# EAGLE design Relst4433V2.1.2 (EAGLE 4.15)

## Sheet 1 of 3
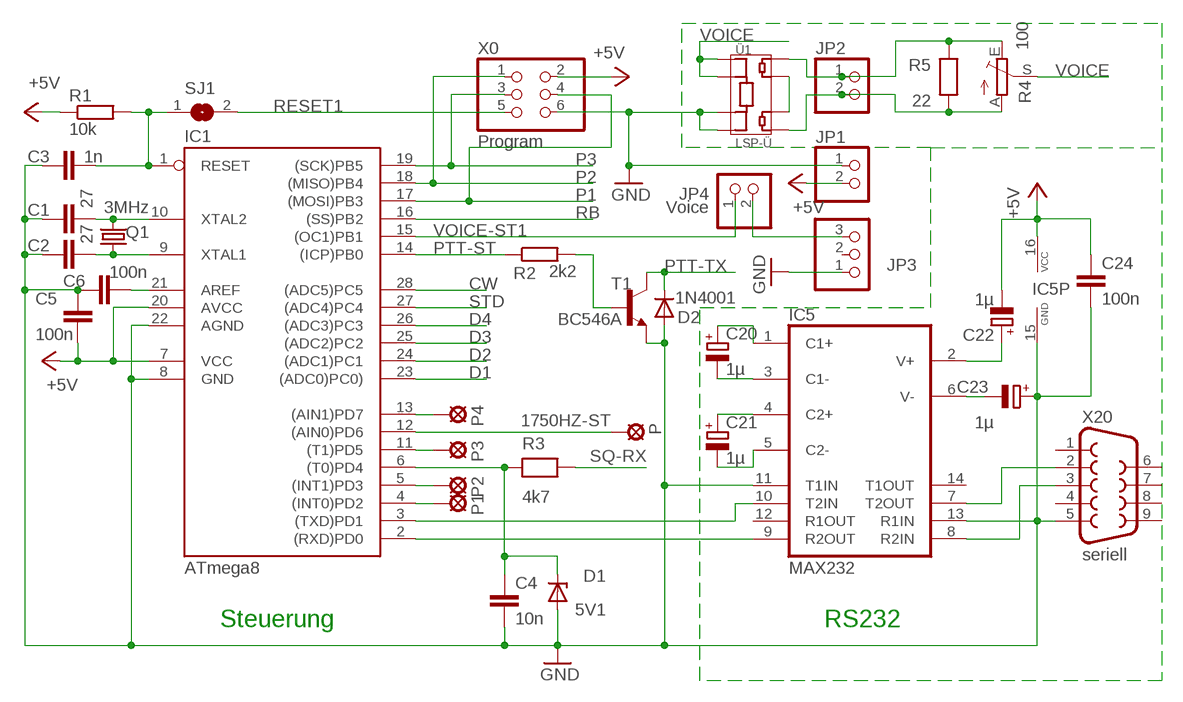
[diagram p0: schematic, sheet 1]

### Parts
C1  27  C-EU025-024X044  [C025-024X044]
C2  27  C-EU025-024X044  [C025-024X044]
C3  1n  C-EU025-024X044  [C025-024X044]
C4  10n  C-EU025-024X044  [C025-024X044]
C5  100n  C-EU025-024X044  [C025-024X044]
C6  100n  C-EU025-024X044  [C025-024X044]
C20  1µ  CPOL-EUE2-5  [E2-5]
C21  1µ  CPOL-EUE2-5  [E2-5]
C22  1µ  CPOL-EUE2-5  [E2-5]
C23  1µ  CPOL-EUE2-5  [E2-5]
C24  100n  C-EU025-024X044  [C025-024X044]
D1  5V1  ZENER-DIODEZD-7.5  [ZDIO-7.5]
D2  1N4001  DIODE-C1702-05  [C1702-05]
IC1  ATmega8  AT90S4433P  [DIL28-3]
IC5  MAX232  [DIL16]
JP1  PINHD-1X2  [1X02]
JP2  PINHD-1X2  [1X02]
JP3  PINHD-1X3  [1X03]
JP4  Voice  PINHD-1X2  [1X02]
P  SE11  [SE11]
P1  SE11  [SE11]
P2  SE11  [SE11]
P3  SE11  [SE11]
P4  SE11  [SE11]
Q1  3MHz  CRYTALHC18U-V  [HC18U-V]
R1  10k  R-EU_0207/2V  [0207/2V]
R2  2k2  R-EU_0414/5V  [0414V]
R3  4k7  RESEU-10  [R-10]
R4  100  TRIM_EU-PT10S  [PT-10S]
R5  22  RESEU-10  [R-10]
SJ1  SJ  [SJ]
T1  BC546A  [TO92-EBC]
X0  Program  PINHD-2X3  [2X03]
X20  seriell  F09H  [F09H]
Ü1  LSP-Ü  LSP-ÜBERTRAGER  [LSP-ÜBERTRAGER]

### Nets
1750HZ-ST: IC1.12((AIN0)PD6) P.MP ; also sheet 2
+5V: C5.2 C22.- C24.1 IC1.7(VCC) IC1.20(AVCC) IC5.16(VCC) JP1.2 R1.1 X0.2 ; also sheet 2,3
AREF: C6.2 IC1.21(AREF)
CW: IC1.28((ADC5)PC5) ; also sheet 2
D1: IC1.23((ADC0)PC0)) ; also sheet 2
D2: IC1.24((ADC1)PC1) ; also sheet 2
D3: IC1.25((ADC2)PC2) ; also sheet 2
D4: IC1.26((ADC3)PC3) ; also sheet 2
GND: C1.1 C2.1 C3.1 C4.2 C5.1 C6.1 C23.+ C24.2 D1.A D2.A IC1.8(GND) IC1.22(AGND) IC5.11(T1IN) IC5.13(R1IN) IC5.15(GND) JP1.1 JP3.1 T1.E X0.6 X20.5 Ü1.9 Ü1.P$10 ; also sheet 2,3
N$1: C1.2 IC1.10(XTAL2) Q1.2
N$2: C2.2 IC1.9(XTAL1) Q1.1
N$3: C21.- IC5.5(C2-)
N$4: IC1.2((RXD)PD0) IC5.9(R2OUT)
N$5: C21.+ IC5.4(C2+)
N$6: IC1.3((TXD)PD1) IC5.10(T2IN)
N$13: C20.+ IC5.1(C1+)
N$14: C20.- IC5.3(C1-)
N$15: IC5.8(R2IN) X20.3
N$16: IC5.7(T2OUT) X20.2
N$22: R2.2 T1.B
N$61: Ü1.2 Ü1.4
N$64: JP2.1 R4.E R5.2 Ü1.5
N$66: JP2.2 R4.A R5.1 Ü1.1
N$73: C22.+ IC5.2(V+)
N$74: C23.- IC5.6(V-)
N$84: IC1.13((AIN1)PD7) P4.MP
N$85: IC1.11((T1)PD5) P3.MP
N$86: IC1.5((INT1)PD3) P2.MP
N$87: IC1.4((INT0)PD2) P1.MP
P1: IC1.17((MOSI)PB3) X0.4 ; also sheet 3
P2: IC1.18((MISO)PB4) X0.1 ; also sheet 3
P3: IC1.19((SCK)PB5) X0.3 ; also sheet 3
PTT-ST: IC1.14((ICP)PB0) R2.1
PTT-TX: D2.C T1.C ; also sheet 3
RB: IC1.16((SS)PB2) ; also sheet 2
RESET: C3.2 IC1.1(RESET) R1.2 SJ1.1 ; also sheet 2
RESET1: SJ1.2 X0.5 ; also sheet 2
SQ-RX: R3.2 ; also sheet 3
SQUELCH: C4.1 D1.C IC1.6((T0)PD4) R3.1
STD: IC1.27((ADC4)PC4) ; also sheet 2
VOICE: R4.S Ü1.7 Ü1.P$6 ; also sheet 2
VOICE-ST: JP3.3 JP4.2
VOICE-ST1: IC1.15((OC1)PB1) JP4.1
Unconnected: IC5.12(R1OUT) IC5.14(T1OUT) JP3.2 X20.1 X20.4 X20.6 X20.7 X20.8 X20.9

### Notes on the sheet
- Steuerung | RS232

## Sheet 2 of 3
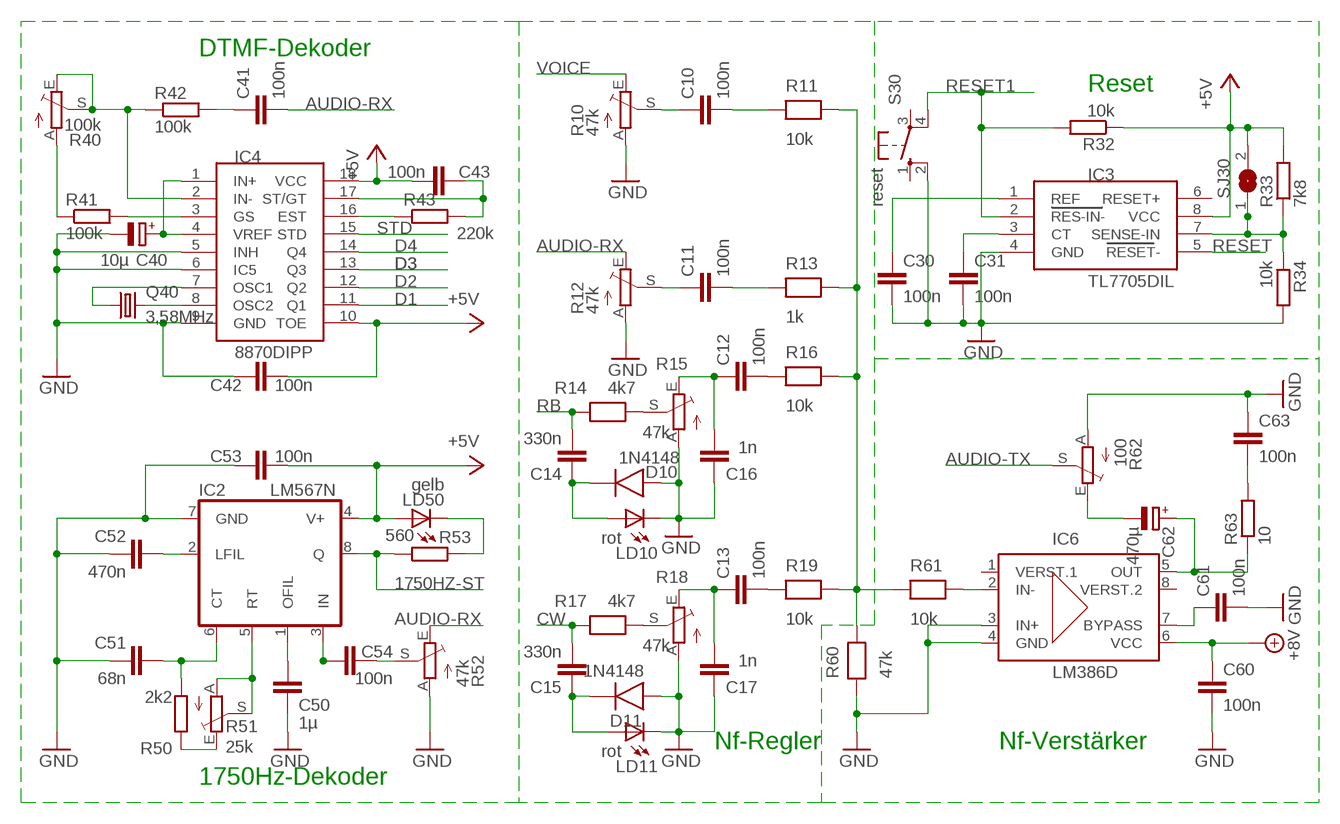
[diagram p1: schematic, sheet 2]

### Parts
C10  100n  C-EU050-025X075  [C050-025X075]
C11  100n  C-EU050-025X075  [C050-025X075]
C12  100n  C-EU050-025X075  [C050-025X075]
C13  100n  C-EU050-025X075  [C050-025X075]
C14  330n  C-EU050-025X075  [C050-025X075]
C15  330n  C-EU050-025X075  [C050-025X075]
C16  1n  C-EU050-025X075  [C050-025X075]
C17  1n  C-EU050-025X075  [C050-025X075]
C30  100n  C-EU050-025X075  [C050-025X075]
C31  100n  C-EU050-025X075  [C050-025X075]
C40  10µ  CPOL-EUE2-5  [E2-5]
C41  100n  C-EU050-025X075  [C050-025X075]
C42  100n  C-EU050-025X075  [C050-025X075]
C43  100n  C-EU050-025X075  [C050-025X075]
C50  1µ  C-EU050-025X075  [C050-025X075]
C51  68n  C-EU050-025X075  [C050-025X075]
C52  470n  C-EU050-025X075  [C050-025X075]
C53  100n  C-EU050-025X075  [C050-025X075]
C54  100n  C-EU050-025X075  [C050-025X075]
C60  100n  C-EU050-025X075  [C050-025X075]
C61  100n  C-EU050-025X075  [C050-025X075]
C62  470µ  CPOL-EUE5-10.5  [E5-10,5]
C63  100n  C-EU050-025X075  [C050-025X075]
D10  1N4148  DIODE-2,5  [D-2,5]
D11  1N4148  DIODE-2,5  [D-2,5]
IC2  LM567N  [DIL08]
IC3  TL7705DIL  [DIL8]
IC4  8870DIPP  [DIL18]
IC6  LM386D  [DIL8]
LD10  rot  LED3MM  [LED3MM]
LD11  rot  LED3MM  [LED3MM]
LD50  gelb  LED3MM  [LED3MM]
Q40  3,58MHz  CRYTALHC18U-V  [HC18U-V]
R10  47k  TRIM_EU-PT10  [PT-10]
R11  10k  RESEU-10  [R-10]
R12  47k  TRIM_EU-PT10  [PT-10]
R13  1k  RESEU-10  [R-10]
R14  4k7  RESEU-10  [R-10]
R15  47k  TRIM_EU-PT10  [PT-10]
R16  10k  RESEU-10  [R-10]
R17  4k7  RESEU-10  [R-10]
R18  47k  TRIM_EU-PT10  [PT-10]
R19  10k  RESEU-10  [R-10]
R32  10k  R-EU_0207/2V  [0207/2V]
R33  7k8  R-EU_0207/2V  [0207/2V]
R34  10k  R-EU_0207/10  [0207/10]
R40  100k  TRIM_EU-PT10  [PT-10]
R41  100k  R-EU_0207/10  [0207/10]
R42  100k  R-EU_0207/10  [0207/10]
R43  220k  R-EU_0207/10  [0207/10]
R50  2k2  R-EU_0207/10  [0207/10]
R51  25k  TRIM_EU-PT10  [PT-10]
R52  47k  TRIM_EU-PT10  [PT-10]
R53  560  R-EU_0207/10  [0207/10]
R60  47k  RESEU-10  [R-10]
R61  10k  RESEU-10  [R-10]
R62  100  TRIM_EU-PT10  [PT-10]
R63  10  R-EU_0207/10  [0207/10]
S30  reset  10-XX  [B3F-10XX]
SJ30  SJ  [SJ]

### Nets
1750HZ-ST: IC2.8(Q) R53.1 ; also sheet 1
+5V: C42.2 C43.2 C53.2 IC2.4(V+) IC3.8(VCC) IC4.10(TOE) IC4.18(VCC) LD50.A R32.1 R33.2 SJ30.2 ; also sheet 1,3
+8V: C60.1 IC6.6(VCC) ; also sheet 3
AUDIO-RX: C41.2 R12.E R52.E ; also sheet 3
AUDIO-TX: R62.S ; also sheet 3
AUDIO-TX-1: R11.2 R13.2 R16.2 R19.2 R60.2 R61.1
CW: C15.2 R17.1 ; also sheet 1
D1: IC4.11(Q1) ; also sheet 1
D2: IC4.12(Q2) ; also sheet 1
D3: IC4.13(Q3) ; also sheet 1
D4: IC4.14(Q4) ; also sheet 1
GND: C16.1 C17.1 C30.2 C31.2 C40.- C42.1 C50.2 C51.1 C52.1 C53.1 C60.2 C61.2 C63.1 D10.1(A) D11.1(A) IC2.7(GND) IC3.4(GND) IC4.5(INH) IC4.6(IC5) IC4.9(GND) IC6.3(IN+) IC6.4(GND) LD10.K(C) LD11.K(C) R10.A R12.A R15.A R18.A R34.2 R52.A R60.1 R62.A S30.2(S1) ; also sheet 1,3
N$8: LD50.K(C) R53.2
N$10: C30.1 IC3.1(REF)
N$12: R17.2 R18.S
N$18: C54.2 R52.S
N$20: C40.+ IC4.1(IN+) IC4.4(VREF)
N$21: C12.1 C16.2 R15.E
N$23: C31.1 IC3.3(CT)
N$24: IC4.8(OSC2) Q40.2
N$25: IC4.7(OSC1) Q40.1
N$26: IC4.2(IN-) R40.E R40.S R42.1
N$27: IC4.3(GS) R41.2
N$28: R40.A R41.1
N$29: C41.1 R42.2
N$30: C13.1 C17.2 R18.E
N$31: IC4.16(EST) R43.1
N$32: C43.1 IC4.17(ST/GT) R43.2
N$33: C10.2 R11.1
N$35: C12.2 R16.1
N$36: C13.2 R19.1
N$37: C54.1 IC2.3(IN)
N$40: C50.1 IC2.1(OFIL)
N$44: IC2.5(RT) R51.A R51.S
N$47: R50.1 R51.E
N$48: C51.2 IC2.6(CT) R50.2
N$51: C52.2 IC2.2(LFIL)
N$65: C11.2 R13.1
N$68: C11.1 R12.S
N$71: C14.1 D10.2(K) LD10.A
N$72: C10.1 R10.S
N$75: C63.2 R63.2
N$76: IC6.2(IN-) R61.2
N$77: C62.- R62.E
N$78: IC3.7(SENSE-IN) R33.1 R34.1 SJ30.1
N$79: C15.1 D11.2(K) LD11.A
N$81: C61.1 IC6.7(BYPASS)
N$82: C62.+ IC6.5(OUT) R63.1
N$89: R14.2 R15.S
RB: C14.2 R14.1 ; also sheet 1
RESET: IC3.5(RESET-) ; also sheet 1
RESET1: IC3.2(RES-IN-) R32.2 S30.4(P1) ; also sheet 1
STD: IC4.15(STD) ; also sheet 1
VOICE: R10.E ; also sheet 1
Unconnected: IC3.6(RESET+) IC6.1(VERST.1) IC6.8(VERST.2) S30.1(S) S30.3(P)

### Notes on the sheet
- DTMF-Dekoder
- Reset
- Nf-Regler | Nf-Verstärker
- 1750Hz-Dekoder

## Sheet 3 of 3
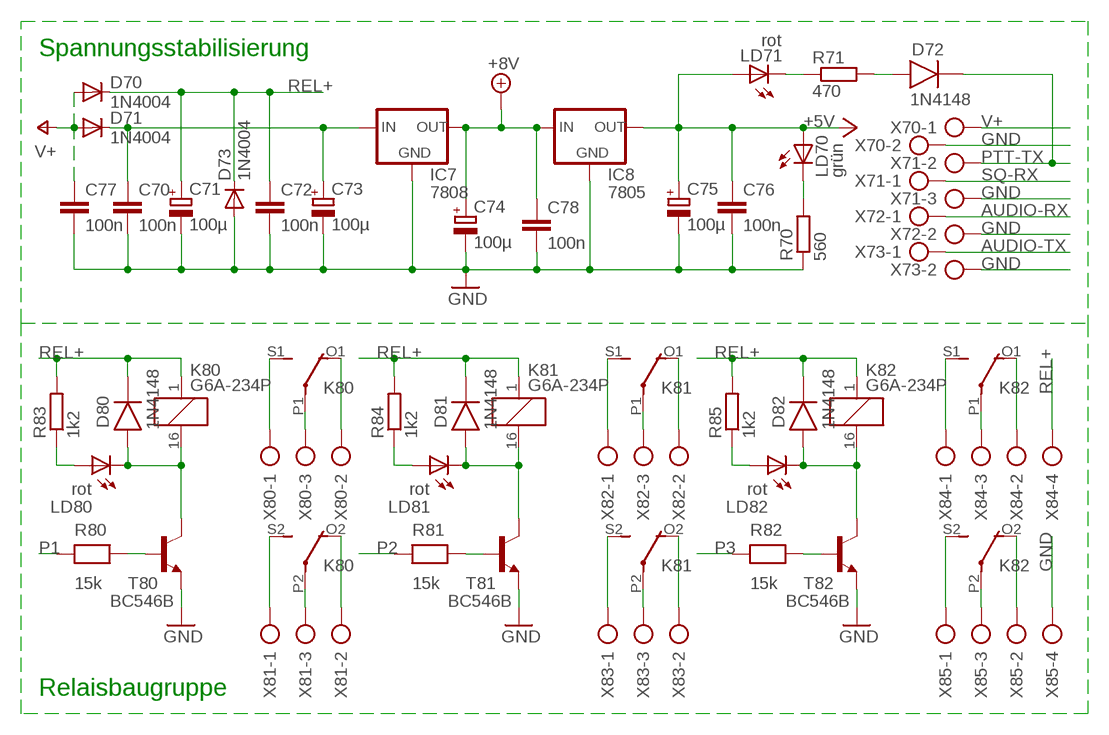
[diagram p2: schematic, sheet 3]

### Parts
C70  100n  C-EU050-025X075  [C050-025X075]
C71  100µ  CPOL-EUE5-10.5  [E5-10,5]
C72  100n  C-EU050-025X075  [C050-025X075]
C73  100µ  CPOL-EUE5-10.5  [E5-10,5]
C74  100µ  CPOL-EUE5-10.5  [E5-10,5]
C75  100µ  CPOL-EUE5-10.5  [E5-10,5]
C76  100n  C-EU050-025X075  [C050-025X075]
C77  100n  C-EU050-025X075  [C050-025X075]
C78  100n  C-EU050-025X075  [C050-025X075]
D70  1N4004  [DO41-10]
D71  1N4004  [DO41-10]
D72  1N4148  DIODE-2,5  [D-2,5]
D73  1N4004  1N4148  [DO35-10]
D80  1N4148  DIODE-7,5  [D-7,5]
D81  1N4148  DIODE-7,5  [D-7,5]
D82  1N4148  DIODE-7,5  [D-7,5]
IC7  7808  78XXS  [78XXS]
IC8  7805  78XXS  [78XXS]
K80  G6A-234P  [G6A-234P]
K81  G6A-234P  [G6A-234P]
K82  G6A-234P  [G6A-234P]
LD70  grün  LED3MM  [LED3MM]
LD71  rot  LED3MM  [LED3MM]
LD80  rot  LED3MM  [LED3MM]
LD81  rot  LED3MM  [LED3MM]
LD82  rot  LED3MM  [LED3MM]
R70  560  R-EU_0207/10  [0207/10]
R71  470  R-EU_0414/5V  [0414V]
R80  15k  RESEU-10  [R-10]
R81  15k  RESEU-10  [R-10]
R82  15k  RESEU-10  [R-10]
R83  1k2  R-EU_0207/2V  [0207/2V]
R84  1k2  R-EU_0207/2V  [0207/2V]
R85  1k2  R-EU_0207/2V  [0207/2V]
T80  BC546B  [TO92-EBC]
T81  BC546B  [TO92-EBC]
T82  BC546B  [TO92-EBC]
X70  AK500/2  [AK500/2]
X71  AK500/3  [AK500/3]
X72  AK500/2  [AK500/2]
X73  AK500/2  [AK500/2]
X80  AK500/3  [AK500/3]
X81  AK500/3  [AK500/3]
X82  AK500/3  [AK500/3]
X83  AK500/3  [AK500/3]
X84  AK500/4  [AK500/4]
X85  AK500/4  [AK500/4]

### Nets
+5V: C75.+ C76.1 IC8.OUT LD70.A LD71.A ; also sheet 1,2
+8V: C74.+ C78.1 IC7.OUT IC8.IN ; also sheet 2
AUDIO-RX: X72.1 ; also sheet 2
AUDIO-TX: X73.1 ; also sheet 2
GND: C70.2 C71.- C72.2 C73.- C74.- C75.- C76.2 C77.2 C78.2 D73.A IC7.GND IC8.GND R70.1 T80.E T81.E T82.E X70.2 X71.3 X72.2 X73.2 X85.4 ; also sheet 1,2
N$7: LD71.K(C) R71.1
N$9: K80.P1(2:P) X80.3
N$11: D72.1(A) R71.2
N$17: K80.P2(3:P) X81.3
N$19: K81.P1(2:P) X82.3
N$34: K81.P2(3:P) X83.3
N$38: K82.P1(2:P) X84.3
N$39: K82.P2(3:P) X85.3
N$41: K80.S1(2:S) X80.1
N$42: K80.O1(2:O) X80.2
N$43: K80.S2(3:S) X81.1
N$45: K80.O2(3:O) X81.2
N$46: K81.S2(3:S) X83.1
N$49: K81.O2(3:O) X83.2
N$50: K81.S1(2:S) X82.1
N$52: K81.O1(2:O) X82.2
N$53: K82.S1(2:S) X84.1
N$54: D80.1(A) K80.16 LD80.K(C) T80.C
N$55: K82.O1(2:O) X84.2
N$56: R81.2 T81.B
N$57: K82.S2(3:S) X85.1
N$58: K82.O2(3:O) X85.2
N$59: D81.1(A) K81.16 LD81.K(C) T81.C
N$60: LD80.A R83.1
N$62: R80.2 T80.B
N$63: R82.2 T82.B
N$67: C70.1 C73.+ D71.C IC7.IN
N$69: D82.1(A) K82.16 LD82.K(C) T82.C
N$70: LD70.K(C) R70.2
N$88: LD81.A R84.1
N$90: LD82.A R85.1
P1: R80.1 ; also sheet 1
P2: R81.1 ; also sheet 1
P3: R82.1 ; also sheet 1
PTT-TX: D72.2(K) X71.2 ; also sheet 1
REL+: C71.+ C72.1 D70.C D73.C D80.2(K) D81.2(K) D82.2(K) K80.1 K81.1 K82.1 R83.2 R84.2 R85.2 X84.4
SQ-RX: X71.1 ; also sheet 1
V+: C77.1 D70.A D71.A X70.1

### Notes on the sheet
- Spannungsstabilisierung
- Relaisbaugruppe

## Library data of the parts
C1-C6 C10-C17 C24 C30 C31 C41-C43 C50-C54 C60 C61 C63 C70 C72 C76-C78 = rcl:C-EU: CAPACITOR, European symbol
C20-C23 C40 C62 C71 C73-C75 = rcl:CPOL-EU: POLARIZED CAPACITOR, European symbol
D1 = diode:ZENER-DIODE: Z-Diode
D2 = diode:DIODE-: DIODE
D10 D11 D72 = discrete:DIODE-2,5
D70 D71 = diode:1N4004: DIODE
D73 = diode:1N4148: DIODE
D80-D82 = discrete:DIODE-7,5
IC1 = atmel:AT90S4433: MICROCONTROLLER 4 Kbytes FLASH 128 bytes SRAM 256 bytes EEPROM UART 6-channel 10 bit ADC
IC2 = linear:*567: TONE DECODER
IC3 = Eigenbaua:TL7705: Power On Reset Generator Precision Voltage Sensor
IC4 = Eigenbaua:8870*: DTMF-Dekoder
IC5 = maxim:MAX232: RS232 TRANSEIVER
IC6 = Eigenbaua:LM386: Nf-Verstärker
IC7 IC8 = v-reg:78XXS: VOLTAGE REGULATOR
JP1 JP2 JP4 = pinhead:PINHD-1X2: PIN HEADER
JP3 = pinhead:PINHD-1X3: PIN HEADER
K80-K82 = relay:G6A-234P: RELAY 2 x switch, 0.3 A/125 V AC, 1 A/30 V DC, Omron
LD10 LD11 LD50 LD70 LD71 LD80-LD82 = led:LED: LED
P P1-P4 = solpad:SE11: SOLDER PAD
Q1 Q40 = crystal:CRYTAL: CRYSTAL
R1 R2 R32-R34 R41-R43 R50 R53 R63 R70 R71 R83-R85 = rcl:R-EU_: RESISTOR, European symbol
R3 R5 R11 R13 R14 R16 R17 R19 R60 R61 R80-R82 = discrete:RESEU-10
R4 R10 R12 R15 R18 R40 R51 R52 R62 = pot:TRIM_EU-: POTENTIOMETER
S30 = switch-omron:10-XX: OMRON SWITCH
SJ1 SJ30 = jumper:SJ: SMD solder JUMPER
T1 T80-T82 = transistor-npn:BC546*: NPN Transistor
X0 = pinhead:PINHD-2X3: PIN HEADER
X20 = con-subd:F09: SUB-D
X70 X72 X73 = con-ptr500:AK500/2: CONNECTOR
X71 X80-X83 = con-ptr500:AK500/3: CONNECTOR
X84 X85 = con-ptr500:AK500/4: CONNECTOR
Ü1 = Eigenbaua:LSP-ÜBERTRAGER*: Laursprecherübertager für Voice-Module

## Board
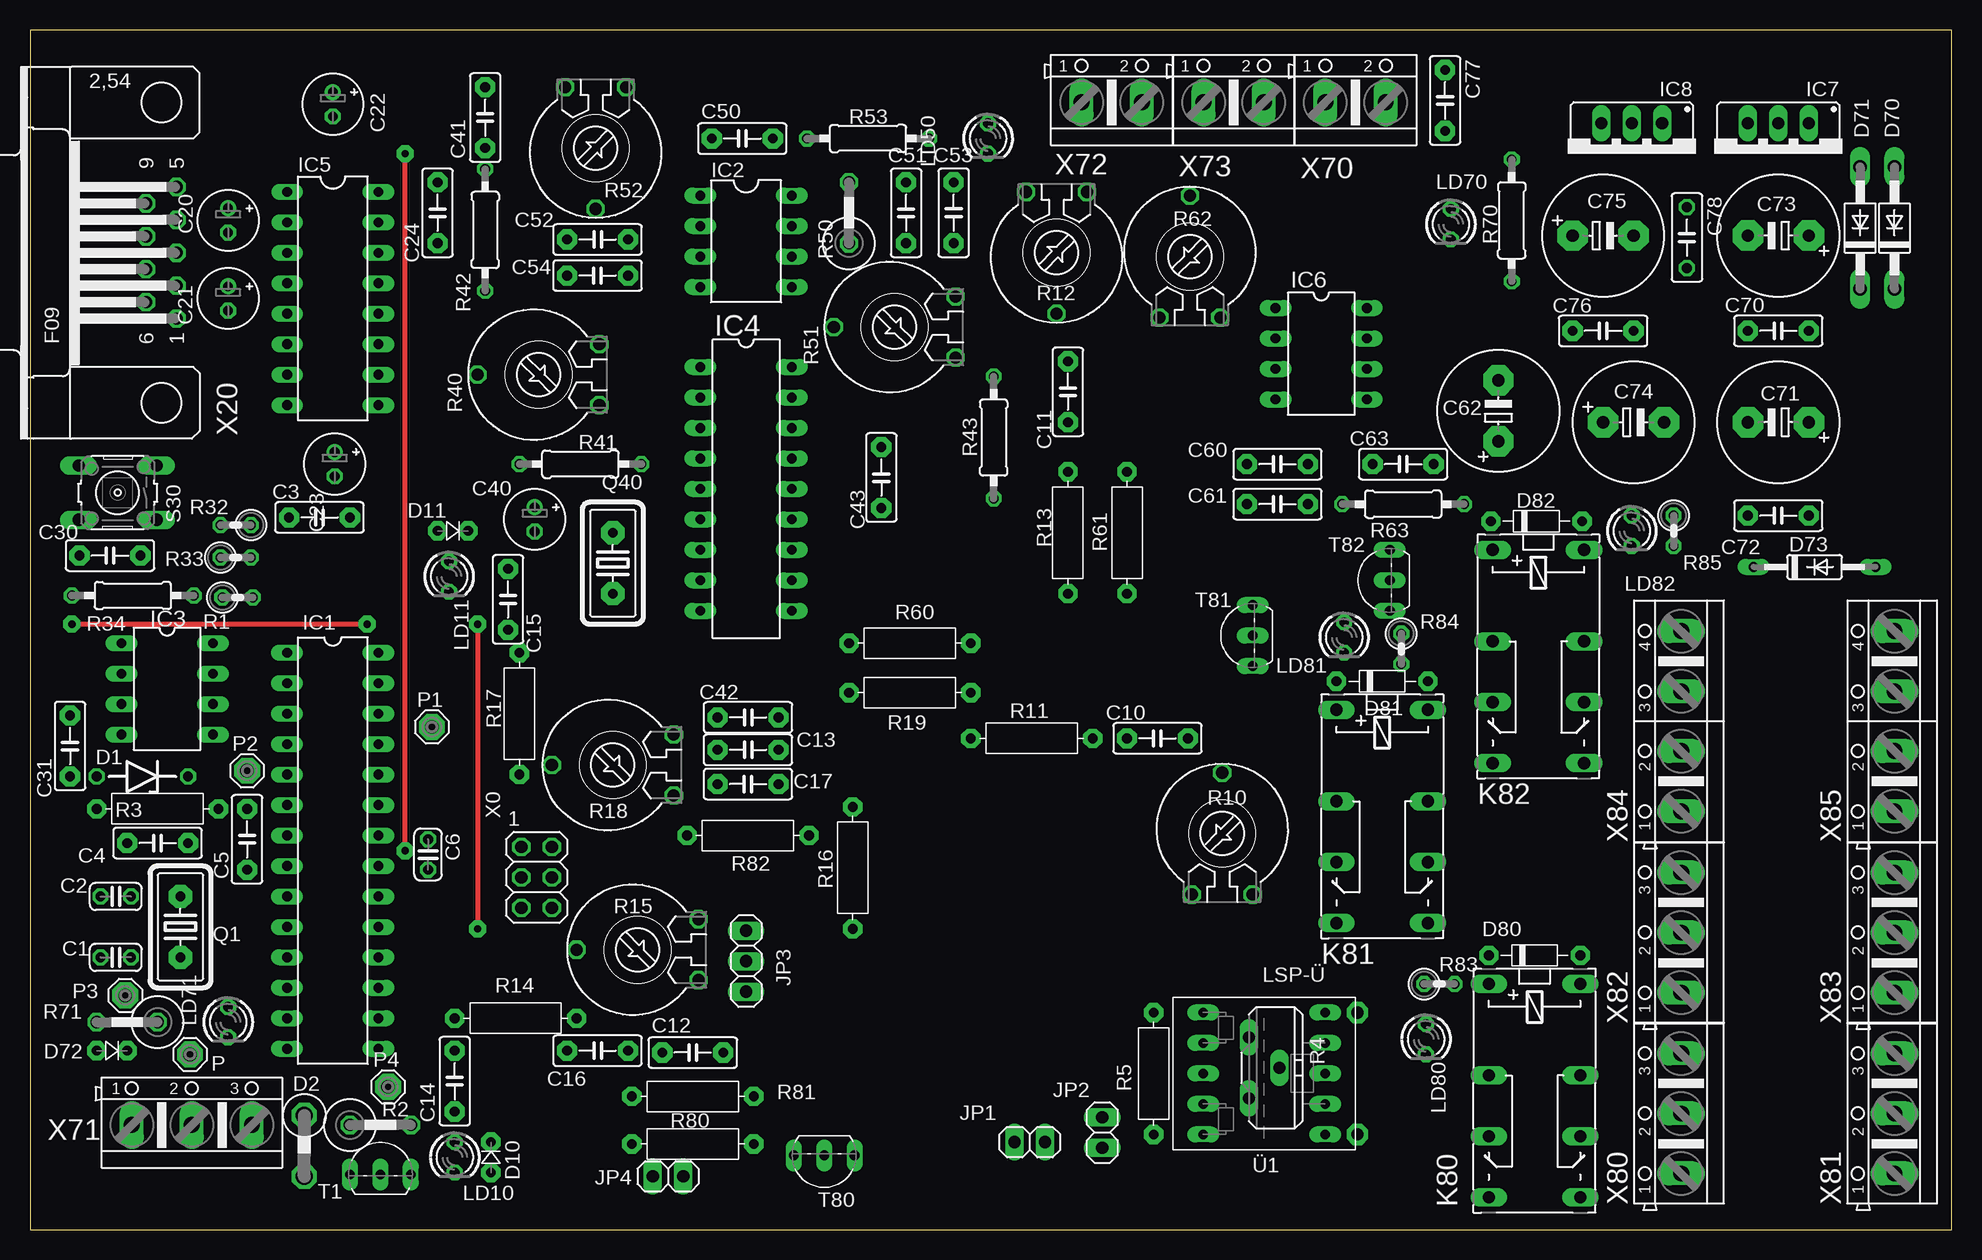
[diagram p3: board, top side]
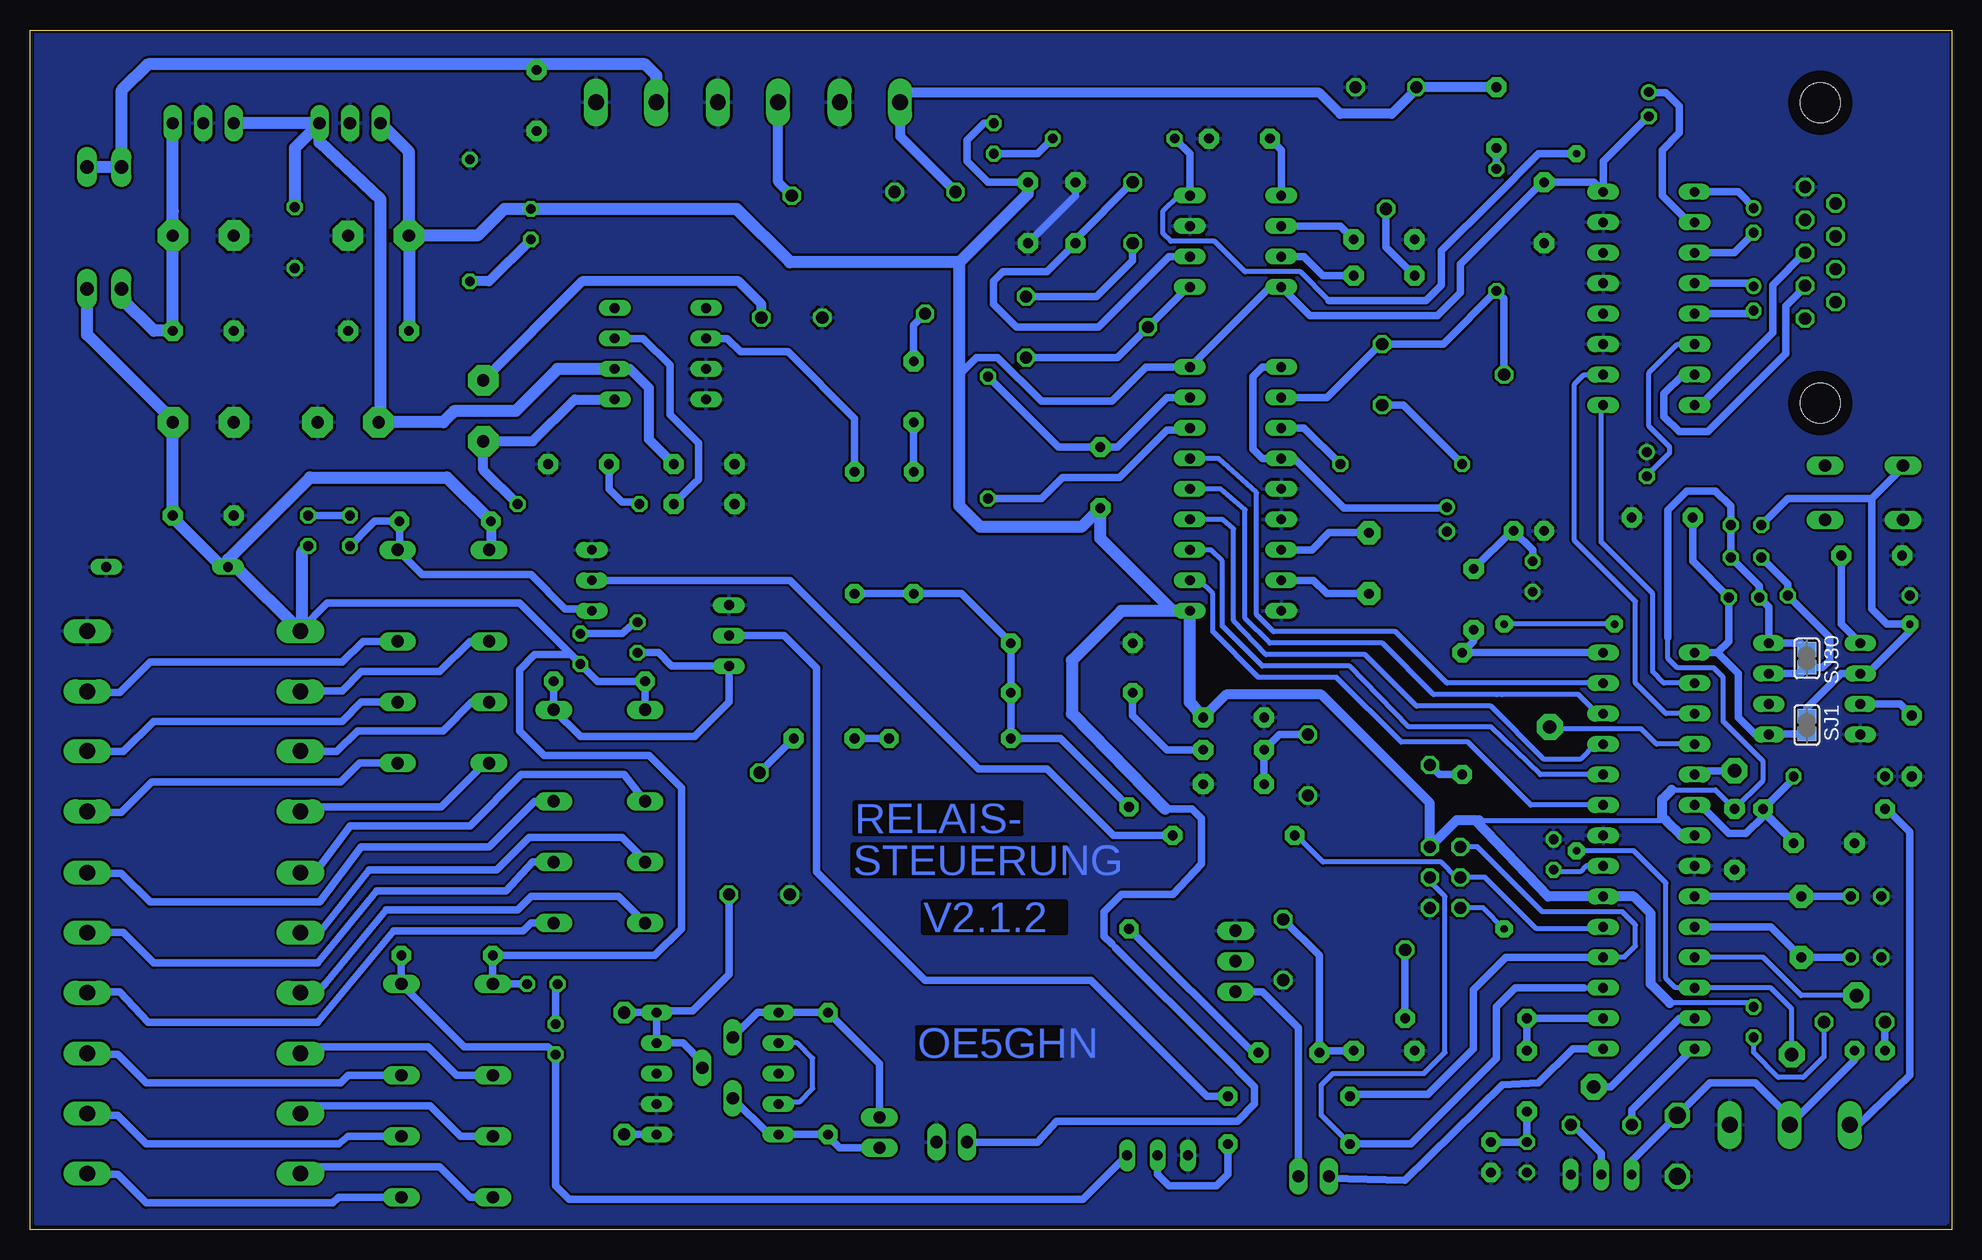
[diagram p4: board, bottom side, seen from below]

Size 160.18 x 100.01 mm. Coordinates in mm from the lower left corner, seen from the top.
Outline: 0,0 160.18,0 160.18,100.01 0,100.01 0,0
Copper layers (1*16): Top 0.035mm / dielectric 1.5mm / Bottom 0.035mm
Design rules "default": minimum track width 16mil, minimum drill 24mil, track to track 8mil, track to pad 8mil, pad to pad 8mil, via to via 8mil, smd to smd 8mil, copper to edge 8mil, drill to drill 10mil, minimum pad ring 10mil, minimum via ring 8mil, stop-mask expansion 4mil, vias tented up to drill 0mil, thermal gap 10mil

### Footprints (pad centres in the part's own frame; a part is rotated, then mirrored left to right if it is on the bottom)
C025-024X044 = drill 0.813 octagon: 1 -1.27,0; 2 1.27,0
C050-025X075@1 = drill 0.813 pad 1.676 octagon: 1 -2.54,0; 2 2.54,0
E2-5 = drill 0.813 pad 1.27 round: + -1.016,0 | drill 0.813 pad 1.27 octagon: - 1.016,0
E5-10,5 = drill 1.016 pad 2.54 octagon: + -2.54,0; - 2.54,0
C050-025X075 = drill 0.813 octagon: 1 -2.54,0; 2 2.54,0
ZDIO-7.5 = drill 0.813 octagon: A 3.81,0; C -3.81,0
C1702-05 = drill 1.397 octagon: A 2.54,0; C -2.54,0
D-2,5 = drill 0.813 pad 1.6 octagon: 1 -1.27,0; 2 1.27,0
DO41-10@1 = drill 1.118 long: A 5.08,0; C -5.08,0
DO35-10 = drill 0.813 long: A 5.08,0; C -5.08,0
D-7,5 = drill 0.813 pad 1.6 octagon: 1 -3.81,0; 2 3.81,0
DIL28-3 = drill 0.813 long: 1 -16.51,-3.81; 2 -13.97,-3.81; 3 -11.43,-3.81; 4 -8.89,-3.81; 5 -6.35,-3.81; 6 -3.81,-3.81; 7 -1.27,-3.81; 8 1.27,-3.81; 9 3.81,-3.81; 10 6.35,-3.81; 11 8.89,-3.81; 12 11.43,-3.81; 13 13.97,-3.81; 14 16.51,-3.81; 15 16.51,3.81; 16 13.97,3.81; 17 11.43,3.81; 18 8.89,3.81; 19 6.35,3.81; 20 3.81,3.81; 21 1.27,3.81; 22 -1.27,3.81; 23 -3.81,3.81; 24 -6.35,3.81; 25 -8.89,3.81; 26 -11.43,3.81; 27 -13.97,3.81; 28 -16.51,3.81
DIL08 = drill 0.813 long: 1 -3.81,-3.81; 2 -1.27,-3.81; 3 1.27,-3.81; 4 3.81,-3.81; 5 3.81,3.81; 6 1.27,3.81; 7 -1.27,3.81; 8 -3.81,3.81
DIL8 = drill 0.813 long: 1 -3.81,-3.81; 2 -1.27,-3.81; 3 1.27,-3.81; 4 3.81,-3.81; 5 3.81,3.81; 6 1.27,3.81; 7 -1.27,3.81; 8 -3.81,3.81
DIL18 = drill 0.813 long: 1 -10.16,-3.81; 2 -7.62,-3.81; 3 -5.08,-3.81; 4 -2.54,-3.81; 5 0,-3.81; 6 2.54,-3.81; 7 5.08,-3.81; 8 7.62,-3.81; 9 10.16,-3.81; 10 10.16,3.81; 11 7.62,3.81; 12 5.08,3.81; 13 2.54,3.81; 14 0,3.81; 15 -2.54,3.81; 16 -5.08,3.81; 17 -7.62,3.81; 18 -10.16,3.81
DIL16 = drill 0.813 long: 1 -8.89,-3.81; 2 -6.35,-3.81; 3 -3.81,-3.81; 4 -1.27,-3.81; 5 1.27,-3.81; 6 3.81,-3.81; 7 6.35,-3.81; 8 8.89,-3.81; 9 8.89,3.81; 10 6.35,3.81; 11 3.81,3.81; 12 1.27,3.81; 13 -1.27,3.81; 14 -3.81,3.81; 15 -6.35,3.81; 16 -8.89,3.81
78XXS = drill 1.016 long: GND 0,-2.54; IN -2.54,-2.54; OUT 2.54,-2.54
1X02 = drill 1.016 long: 1 -1.27,0; 2 1.27,0
1X03 = drill 1.016 long: 1 -2.54,0; 2 0,0; 3 2.54,0
G6A-234P = drill 1.016 long: 1 -3.81,-3.81; 16 -3.81,3.81; O1 8.89,-3.81; O2 8.89,3.81; P1 3.81,-3.81; P2 3.81,3.81; S1 13.97,-3.81; S2 13.97,3.81
LED3MM = drill 0.813 octagon: A -1.27,0; K 1.27,0
SE11 = drill 1.118 pad 2.159 octagon: MP 0,0
HC18U-V = drill 0.813 pad 1.93 octagon: 1 -2.54,0; 2 2.54,0
0207/2V = drill 0.813 octagon: 1 -1.27,0; 2 1.27,0
0414V = drill 1.016 octagon: 1 -2.54,0; 2 2.54,0
R-10 = drill 0.813 pad 1.6 octagon: 1 -5.08,0; 2 5.08,0
PT-10S = drill 1.016 long: A -2.54,-1.27; E 2.54,-1.27; S 0,1.27
PT-10 = drill 1.016 octagon: A -2.54,-5.08; E 2.54,-5.08; S 0,5.08
0207/10 = drill 0.813 octagon: 1 -5.08,0; 2 5.08,0
B3F-10XX = drill 1.016 long: 1 -3.251,2.261; 2 3.251,2.261; 3 -3.251,-2.261; 4 3.251,-2.261
SJ = smd 1.168 x 1.6: 1 -0.762,0; 2 0.762,0
TO92-EBC = drill 0.813 long: B 0,-1.27; C -2.54,-1.27; E 2.54,-1.27
2X03 = drill 1.016 octagon: 1 -2.54,-1.27; 2 -2.54,1.27; 3 0,-1.27; 4 0,1.27; 5 2.54,-1.27; 6 2.54,1.27
F09H = drill 1.016 octagon: 1 -5.486,-1.27; 2 -2.743,-1.27; 3 0,-1.27; 4 2.743,-1.27; 5 5.486,-1.27; 6 -4.115,1.27; 7 -1.372,1.27; 8 1.372,1.27; 9 4.115,1.27 | hole 3.302: -12.522,0; 12.522,0
AK500/2 = drill 1.321 long: 1 -2.515,0; 2 2.515,0
AK500/3 = drill 1.321 long: 1 -5.004,0; 2 0,0; 3 5.004,0
AK500/4 = drill 1.321 long: 1 -7.518,0; 2 -2.489,0; 3 2.489,0; 4 7.518,0
LSP-ÜBERTRAGER = drill 0.813 pad 0.61 long: 1 5.08,-5.08; 2 5.08,-2.54; 4 5.08,2.54; 5 5.08,5.08; 7 -5.08,-2.54; 9 -5.08,2.54; P$1 5.08,0; P$6 -5.08,-5.08; P$8 -5.08,0; P$10 -5.08,5.08

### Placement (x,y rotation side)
C1  7.14,22.7 0 top
C2  7.14,27.78 0 top
C3  1n  [C050-025X075@1]  24.13,59.37 180 top
C4  10n  [C050-025X075@1]  10.64,32.23 180 top
C5  100n  [C050-025X075@1]  18.1,32.54 90 top
C6  33.18,31.27 270 top
C10  100n  [C050-025X075@1]  93.98,40.96 180 top
C11  100n  [C050-025X075@1]  86.52,69.85 270 top
C12  100n  [C050-025X075@1]  55.25,14.76 0 top
C13  100n  [C050-025X075@1]  59.85,40.01 0 top
C14  330n  [C050-025X075@1]  35.4,12.38 90 top
C15  330n  [C050-025X075@1]  39.85,52.55 270 top
C16  1n  [C050-025X075@1]  47.31,14.92 0 top
C17  1n  [C050-025X075@1]  59.85,37.15 180 top
C20  16.51,84.14 270 top
C21  16.51,77.63 270 top
C22  25.24,93.82 270 top
C23  25.4,63.82 270 top
C24  100n  [C050-025X075@1]  33.97,84.77 270 top
C30  100n  [C050-025X075@1]  6.67,56.2 180 top
C31  100n  [C050-025X075@1]  3.33,40.32 270 top
C40  42.07,59.21 270 top
C41  100n  [C050-025X075@1]  37.94,92.71 90 top
C42  100n  [C050-025X075@1]  59.85,42.7 0 top
C43  100n  [C050-025X075@1]  70.96,62.71 270 top
C50  1µ  [C050-025X075@1]  59.37,90.96 0 top
C51  68n  [C050-025X075@1]  73.03,84.77 270 top
C52  470n  [C050-025X075@1]  47.31,82.55 0 top
C53  100n  [C050-025X075@1]  76.99,84.77 90 top
C54  100n  [C050-025X075@1]  47.31,79.53 180 top
C60  100n  [C050-025X075@1]  103.98,63.82 180 top
C61  100n  [C050-025X075@1]  103.98,60.48 180 top
C62  122.4,68.26 90 top
C63  100n  [C050-025X075@1]  114.46,63.82 180 top
C70  100n  [C050-025X075@1]  145.73,74.93 180 top
C71  145.73,67.31 180 top
C72  100n  [C050-025X075@1]  145.73,59.53 180 top
C73  145.73,82.87 180 top
C74  133.67,67.31 0 top
C75  131.13,82.87 0 top
C76  100n  [C050-025X075@1]  131.13,74.93 0 top
C77  100n  [C050-025X075@1]  117.95,94.14 270 top
C78  138.11,82.71 270 top
D1  9.37,37.78 180 top
D2  22.86,6.98 270 top
D10  38.42,6.03 90 top
D11  35.24,58.26 0 top
D70  1N4004  [DO41-10@1]  155.42,83.5 90 top
D71  1N4004  [DO41-10@1]  152.56,83.5 90 top
D72  6.83,14.92 0 top
D73  148.75,55.25 0 top
D80  125.41,22.86 180 top
D81  112.71,45.72 180 top
D82  125.57,59.05 180 top
IC1  25.24,31.59 270 top
IC2  59.69,82.39 270 top
IC3  11.43,45.09 270 top
IC4  59.69,61.75 270 top
IC5  25.24,77.63 270 top
IC6  107.63,73.02 270 top
IC7  145.73,89.69 180 top
IC8  133.51,89.69 180 top
JP1  83.34,7.3 180 top
JP2  89.38,8.1 90 top
JP3  59.69,22.38 270 top
JP4  53.18,4.45 0 top
K80  125.41,16.67 270 top
K81  112.71,39.53 270 top
K82  125.73,52.86 270 top
LD10  35.4,6.03 270 top
LD11  34.92,54.45 270 top
LD50  79.85,90.96 270 top
LD70  118.43,83.82 270 top
LD71  16.51,17.3 270 top
LD80  116.36,15.88 270 top
LD81  109.54,49.37 270 top
LD82  133.51,58.26 270 top
P  13.34,14.6 0 top
P1  33.5,41.91 0 top
P2  18.1,38.26 0 top
P3  7.94,19.53 0 top
P4  29.84,11.91 0 top
Q1  12.54,25.24 270 top
Q40  48.58,55.56 270 top
R1  17.3,52.7 0 top
R2  29.21,8.73 0 top
R3  10.64,35.08 180 top
R4  102.87,13.49 270 top
R5  93.66,13.02 270 top
R10  99.38,33.02 0 top
R11  83.5,40.96 180 top
R12  85.57,81.44 180 top
R13  86.52,58.1 270 top
R14  40.48,17.62 0 top
R15  50.64,23.34 90 top
R16  68.58,30.16 90 top
R17  40.8,43.02 270 top
R18  48.58,38.73 90 top
R19  73.34,44.77 0 top
R32  17.14,58.74 180 top
R33  17.15,56.04 0 top
R34  8.57,52.86 180 top
R40  42.39,71.28 90 top
R41  45.88,63.82 0 top
R42  37.94,83.34 90 top
R43  80.33,66.04 90 top
R50  2k2  [0414V]  68.26,84.77 90 top
R51  72.07,75.25 90 top
R52  47.15,90.17 180 top
R53  69.85,90.96 0 top
R60  73.34,48.9 0 top
R61  91.44,58.1 90 top
R62  96.68,81.12 0 top
R63  114.46,60.48 180 top
R70  123.51,84.14 270 top
R71  8.1,17.3 180 top
R80  55.24,7.14 0 top
R81  55.24,11.11 0 top
R82  59.85,32.86 0 top
R83  117.47,20.48 0 top
R84  114.3,48.42 270 top
R85  137,58.26 270 top
S30  7.3,61.44 180 top
SJ1  12.07,42.07 90 bottom
SJ30  12.06,47.63 90 bottom
T1  29.21,5.87 0 top
T80  66.2,4.92 180 top
T81  100.65,49.53 90 top
T82  112.08,54.13 90 top
X0  42.23,29.37 270 top
X20  10.95,81.44 90 top
X70  110.49,93.98 0 top
X71  13.49,8.73 0 top
X72  90.17,93.98 0 top
X73  100.33,93.98 0 top
X80  137.64,9.68 90 top
X81  155.42,9.68 90 top
X82  137.64,24.76 90 top
X83  155.42,24.76 90 top
X84  137.64,42.39 90 top
X85  155.42,42.39 90 top
Ü1  102.87,13.02 180 top

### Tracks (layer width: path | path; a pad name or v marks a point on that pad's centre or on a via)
1750HZ-ST  (via drill 0.61 pad 1.42)
  Top 0.406: v31.27,31.59 v31.27,89.69
  Bottom 0.406: IC2.8 63.66,86.2 64.45,86.2 65.72,84.93 65.72,83.03 65.09,82.39 61.44,82.39 58.9,79.85 54.29,79.85 51.91,77.47 | IC1.12 | IC1.12 | IC1.12 23.02,20.16 23.81,20.95 23.81,28.89 26.51,31.59 31.43,31.59 v31.27,31.59 | IC1.12 15.08,20.16 13.34,18.41 P.MP | P.MP
  Bottom 0.61: R53.1 63.5,89.69 IC2.8 63.66,86.2 | 51.91,77.47 43.81,77.47 42.55,78.74 42.55,81.6 38.26,85.88 | 38.26,85.88 34.45,89.69 32.07,89.69 v31.27,89.69 | 38.26,85.88 | 63.66,86.2
+5V
  Bottom 0: IC1.7 | IC1.7
  Bottom 0.406: 24.13,34.45 23.81,34.13 39.37,34.13 | 23.34,36.67 19.68,36.67 C5.2 15.72,37.47 15.72,39.05 19.05,42.39 19.05,46.04 19.84,46.83 22.86,46.83 23.65,47.62 23.65,49.37 | IC4.10 | IC4.10 | 70.01,23.81 69.69,23.5 | LD71.A 16.83,18.89 23.5,18.89 | IC5.16 | C43.2
  Bottom 0.61: 63.66,51.59 | 63.66,51.59 IC4.10 | 33.5,87.31 34.13,87.31 | 33.5,87.31 C24.1 | 33.5,87.31 29.84,87.31 IC5.16 29.05,89.06 25.24,92.87 C22.- | 63.66,51.59 64.93,51.59 | 70.8,60.17 | 70.8,60.17 C43.2 | 70.96,60.01 70.8,60.17 | IC4.18 67.15,71.91 70.01,69.06 75.88,69.06 79.53,72.71 81.28,72.71 82.71,71.28 | 62.23,42.86 C42.2 | 65.56,35.08 63.34,35.08 62.55,34.29 62.55,30.48 64.93,27.94 69.22,27.94 70.64,26.51 70.64,24.45 70.01,23.81 | C24.1 34.45,87.15 | C24.1 33.5,87.31 | 34.13,87.31 34.45,87.31 | 34.13,87.31 C24.1 | IC3.8 | SJ30.2 12.57,48.9 IC3.8 | R1.1 | IC3.8 15.24,51.91 R1.1 | R1.1 16.03,53.66 R33.2 | R32.1 | R33.2 R32.1 | R32.1 | 23.65,49.37 23.65,60.01 22.07,61.59 19.68,61.59 18.41,60.33 R33.2 | R33.2 | 34.13,87.31 40.96,80.49 40.96,78.11 42.86,76.2 53.5,76.2 IC2.4 | 69.69,23.5 60.96,14.76 58.1,11.91 58.1,10.48 59.53,9.05 74.61,9.05 76.2,7.3 JP1.2 | IC1.20 | IC1.20 | IC2.4 | IC4.18 | IC4.18 | 56.04,78.58 56.83,78.58 IC4.18 | 56.04,78.58 IC2.4 | 56.04,78.58 | 56.04,78.58 IC2.4 | C53.2 80.33,87.31 82.07,89.06 82.07,90.81 80.64,92.23 LD50.A | LD50.A | LD50.A
  Bottom 0.813: IC1.7 22.54,32.86 23.81,34.13 | 24.13,34.45 24.13,35.88 23.34,36.67 | 62.23,42.86 60.48,44.61 52.55,44.61 43.5,35.56 X0.2 | 23.5,18.89 25.08,20.48 25.08,26.35 26.51,27.78 IC1.20 33.66,27.78 39.69,34.13 | X0.2 | X0.2 41.27,34.13 39.69,34.13 | 39.69,34.13 39.37,34.13
  Bottom 1.016: LD70.A | LD70.A 118.43,85.25 118.59,85.09 LD70.A | 64.93,51.59 70.96,57.63 70.96,60.01 | C43.2 72.55,58.58 80.96,58.58 82.71,60.33 82.71,71.28 82.71,80.64 | IC4.10 63.5,43.97 C42.2 | 65.56,35.08 73.34,43.02 73.34,47.47 69.22,51.59 IC4.10 | LD70.A 120.65,85.09 122.87,82.87 C75.+ | C75.+ C76.1 | LD70.A 101.28,85.09 96.84,80.64 82.71,80.64 | 82.71,80.64 76.99,86.36 C53.2 | C53.2 | 131.13,92.39 IC8.OUT | IC8.OUT | C75.+ 128.59,89.85 IC8.OUT
+8V
  Bottom 0.813: C60.1 108.58,65.88 108.58,70.17 110.17,71.75 IC6.6 | IC6.6
  Bottom 1.016: 124.94,68.1 125.73,67.31 131.29,67.31 | 124.94,68.1 | 124.94,68.1 124.78,68.26 119.7,68.26 116.2,71.75 111.6,71.75 | 111.6,71.75 | IC6.6 111.6,71.75 | IC8.IN | IC8.IN 136.05,90.65 130.97,85.88 130.97,67.31 131.13,67.15 131.29,67.31 | IC7.OUT | IC7.OUT | IC8.IN IC7.OUT | 131.29,67.31 C74.+ | C78.1 138.11,90.17 IC8.IN
AREF
  Bottom 0.406: IC1.21 30.48,30.32 30.96,29.84 33.02,29.84 C6.2 | C6.2
AUDIO-RX
  Bottom 0.813: R52.E | C41.2 R52.E | R52.E 44.61,95.09 46.67,93.03 50.96,93.03 52.7,94.77 86.84,94.77 87.63,93.98 | 87.63,93.98 | 87.63,93.98 X72.1 87.66,91.15 R12.E | R12.E
AUDIO-TX
  Bottom 0.813: R62.S | X73.1 97.81,87.34 R62.S
AUDIO-TX-1
  Bottom 0.61: R13.2 86.36,53.02 | R13.2 R61.1 | 77.95,40.96 R11.2 | 77.95,40.96 78.42,41.43 | R16.2 74.3,40.96 77.95,40.96 | R60.2 R19.2 78.42,41.43 | R60.2 78.42,49.05 | 78.42,41.43 78.42,41.27 | R60.2 | R13.2 82.55,53.02 R60.2
CW
  Bottom 0.61: IC1.28 R17.1 | R17.1 | R17.1 | C15.2 39.85,49.05 R17.1
D1
  Bottom 0.406: IC1.23 35.08,35.4 40.32,40.64 45.88,40.64 51.28,46.04 57.78,46.04 61.59,49.85 61.59,53.02 62.71,54.13 IC4.11 | IC4.11 | IC4.11
D2
  Bottom 0.406: IC1.24 34.29,37.94 38.42,41.91 45.24,41.91 50.16,46.99 57.47,46.99 60.8,50.32 60.8,55.72 61.75,56.67 63.66,56.67 | 63.66,56.67 | 63.66,56.67 IC4.12
D3
  Bottom 0.406: IC1.25 29.69,40.48 30.96,39.21 33.97,39.21 38.42,43.66 | 38.42,43.66 | 38.42,43.66 44.61,43.66 48.9,47.94 57.15,47.94 59.85,50.8 59.85,58.42 60.8,59.21 IC4.13 | IC4.13 | IC4.13
D4
  Bottom 0.406: IC1.26 29.53,43.02 31.11,44.61 37.47,44.61 37.94,44.61 43.18,44.61 47.47,48.9 56.83,48.9 58.9,50.96 58.9,60.01 60.96,61.75 IC4.14 | IC4.14 | IC4.14
GND
  Bottom 0.61: C5.1 18.41,30.32 | C51.1 73.03,86.2 C53.1 | JP1.1 84.77,6.99 | C52.1 44.77,82.39 | IC2.7 63.66,83.66 | C1.1 | C2.1 | D1.A | IC5.15
  Bottom 1.016: 143.19,68.1 C71.- | C71.- 143.35,67.15 | C71.-
  pour Bottom: 0.32,99.69 0.32,0.64 0.48,0.48 159.7,0.48 159.7,99.69
N$1
  Bottom 0.61: IC1.10 | IC1.10 | IC1.10 15.08,25.24 Q1.2 C1.2 | C1.2
N$2
  Bottom 0.61: Q1.1 IC1.9 | Q1.1 | C2.2 | C2.2 Q1.1
N$3
  Bottom 0.61: 16.35,76.68 C21.- 16.35,76.52 16.51,76.36 21.59,76.36 | 21.59,76.36 | 21.59,76.36 IC5.5 | 21.59,76.36 21.59,76.52
N$4
  Bottom 0.406: IC1.2 23.97,45.56 24.92,46.51 24.92,53.02 28.42,56.52 | 29.21,68.74 | 29.21,68.74 IC5.9 | 28.42,56.52 | 28.42,56.52 29.21,57.31 29.21,68.74
  Bottom 0.61: IC5.9 | IC5.9
N$5
  Bottom 0.61: C21.+ 16.35,78.58 16.67,78.9 IC5.4 | IC5.4
N$6
  Bottom 0.406: IC1.3 23.81,43.02 26.35,45.56 26.35,52.39 31.43,57.47 31.43,70.48 30.64,71.28 29.21,71.28 | 29.21,71.28 | 29.21,71.28 IC5.10
  Bottom 0.61: 28.89,71.28 | 28.89,71.28 IC5.10 28.89,71.28 | 28.89,71.28 28.89,71.44
N$7
  Bottom 0.406: LD71.K 16.51,14.76 14.45,12.7 12.38,12.7 10.64,14.45 R71.1 | R71.1
N$8
  Bottom 0.61: LD50.K 76.2,89.69 R53.2
N$9
  Bottom 0.61: K80.P1 124.62,12.86 127,15.24 137.16,15.24 137.64,14.76 | 137.64,14.76 | 137.64,14.76 X80.3
N$10
  Bottom 0.61: IC3.1 | C30.1 9.21,50.48 IC3.1
N$11
  Bottom 0.61: R71.2 | D72.1 R71.2 | R71.2
N$12
  Bottom 0.61: R18.S | R17.2 42.7,37.94 R18.S
N$13
  Bottom 0.61: C20.+ 16.35,85.09 17.78,86.52 21.59,86.52 | 21.59,86.52 IC5.1 | 21.59,86.52
N$14
  Bottom 0.61: C20.- 16.35,83.19 18.1,81.44 21.59,81.44 | 21.59,81.44 | 21.59,81.44 IC5.3
N$15
  Bottom 0.61: X20.3 | X20.3 14.92,78.74 14.92,74.77 20.95,68.74 IC5.8 | IC5.8
N$16
  Bottom 0.61: 21.59,71.28 22.38,71.28 23.97,69.69 23.97,67.79 22.7,66.52 20.32,66.52 13.81,73.03 13.81,76.99 12.22,78.58 X20.2 | 21.59,71.28 IC5.7 21.59,71.28 | 21.59,71.28 | 21.59,71.28 21.59,71.12
N$17
  Bottom 0.61: K80.P2 133.67,12.86 134.3,12.22 150.5,12.22 152.88,14.61 155.26,14.61 155.49,14.37 X81.3
N$18
  Bottom 0.61: R52.S | C54.2 47.15,81.92 R52.S
N$19
  Bottom 0.61: K81.P1 | K81.P1 | K81.P1 110.65,37.94 119.22,37.94 123.51,33.66 133.51,33.66 136.37,29.84 137.48,29.84 137.64,29.69 | 137.64,29.69 | 137.64,29.69 X82.3
N$20
  Bottom 0.61: IC4.1 57.47,71.91 58.26,71.12 58.26,65.09 57.47,64.29 IC4.4 | IC4.4 | IC4.4 | IC4.4 54.77,64.29 50.64,60.17 42.23,60.17 42.07,60.33 | 42.07,60.33 | C40.+ 42.07,60.33
N$21
  Bottom 0.61: C12.1 | R15.E 52.7,22.86 C12.1 | C16.2 52.55,14.92 C12.1
N$22
  Bottom 0.61: R2.2 31.75,8.89 29.21,6.35 T1.B | T1.B
N$23
  Bottom 0.61: C31.1 | IC3.3 4.29,43.81 C31.1
N$24
  Bottom 0.61: Q40.2 52.07,53.02 53.18,54.13 IC4.8 | IC4.8 | IC4.8
N$25
  Bottom 0.61: Q40.1 51.91,58.1 53.34,56.67 IC4.7 | IC4.7 | IC4.7
N$26
  Bottom 0.61: IC4.2 52.07,69.37 47.47,73.98 R40.E 42.39,73.82 R42.1 | R42.1 | R40.S 37.31,77.63 R42.1
N$27
  Bottom 0.61: IC4.3 | IC4.3 | IC4.3 53.98,66.83 R41.2
N$28
  Bottom 0.61: R40.A 45.72,68.74 R41.1
N$29
  Bottom 0.61: R42.2 | R42.2 C41.1
N$30
  Bottom 0.61: R18.E 56.04,41.27 C13.1 C17.2
N$31
  Bottom 0.61: R43.1 75.88,60.96 74.14,62.71 69.37,62.71 65.41,66.67 63.82,66.67 63.66,66.83 63.66,66.67 IC4.16 | IC4.16 | IC4.16
N$32
  Bottom 0.61: R43.2 | IC4.17 65.41,69.37 69.53,65.25 71.12,65.25 | 71.12,65.25 | 71.12,65.25 C43.1 74.45,65.25 R43.2
N$33
  Bottom 0.61: R11.1 88.74,40.96 R11.1 C10.2
N$34
  Bottom 0.61: X83.3 155.5,29.61 155.57,29.69 152.56,29.69 150.18,27.3 136.05,27.3 132.56,31.91 121.92,31.91 118.11,35.72 K81.P2 | K81.P2
N$35
  Bottom 0.61: R16.1 58.26,14.76 58.1,14.76 C12.2
N$36
  Bottom 0.61: R19.1 68.26,42.86 65.41,40.01 C13.2
N$37
  Bottom 0.61: C54.1 52.39,79.53 53.98,81.12 55.72,81.12 | 55.72,81.12 | 55.72,81.12 IC2.3 | IC2.3 | IC2.3
N$38
  Bottom 0.61: K82.P1 123.51,49.05 126.05,46.51 132.56,46.51 134.14,44.93 137.64,44.93 | 137.64,44.93 | 137.64,44.93 X84.3
N$39
  Bottom 0.61: K82.P2 132.4,49.05 134.14,47.31 150.18,47.31 152.72,44.77 155.26,44.77 155.42,44.93 X85.3
N$40
  Bottom 0.61: C50.1 55.88,90.01 IC2.1 | IC2.1 | IC2.1
N$41
  Bottom 0.61: K80.S1 123.51,2.7 126.05,5.24 137,5.24 137.64,4.6 | 137.64,4.6 | 137.64,4.6 X80.1
N$42
  Bottom 0.61: K80.O1 124.3,7.78 126.84,10.32 137,10.32 X80.2 | X80.2
N$43
  Bottom 0.61: K80.S2 134.46,2.7 134.94,2.22 150.5,2.22 152.88,4.6 155.57,4.6 155.42,4.45 X81.1
N$44
  Bottom 0.61: IC2.5 63.66,78.58 R51.S 69.53,72.71 R51.A | IC2.5 | IC2.5
N$45
  Bottom 0.61: K80.O2 133.67,7.78 134.46,7.14 150.5,7.14 152.88,9.53 155.89,9.53 155.57,9.37 X81.2
N$46
  Bottom 0.61: X83.1 155.42,19.68 155.57,19.84 152.72,19.84 150.34,17.3 136.21,17.3 129.86,24.92 119.06,24.92 118.43,25.56 K81.S2 | K81.S2
N$47
  Bottom 0.61: R51.E 71.28,77.79 68.26,80.8 R50.1 | R50.1
N$48
  Bottom 0.61: IC2.6 | 63.66,81.12 65.25,81.12 71.12,75.25 77.95,75.25 79.85,77.15 79.85,79.06 79.06,79.85 75.41,79.85 C51.2 | 63.66,81.12 IC2.6 | C51.2 | R50.2 | C51.2 73.03,82.55 R50.2 | 63.66,81.12 | IC2.6 63.66,81.12
N$49
  Bottom 0.61: 155.57,24.61 | 155.57,24.61 X83.2 | X83.2 152.4,24.77 149.86,22.23 136.21,22.23 131.29,28.26 120.49,28.26 118.27,30.64 K81.O2 | X83.2 155.57,24.61 | K81.O2
N$50
  Bottom 0.61: K81.S1 | K81.S1 | K81.S1 111.12,27.78 118.43,27.78 119.54,26.67 130.49,26.67 135.57,20.48 136.21,19.84 137.48,19.84 137.64,19.68 | 137.64,19.68 | 137.64,19.68 X82.1
N$51
  Bottom 0.61: 56.04,83.66 | IC2.2 56.04,83.66 | IC2.2 | C52.2 50.96,83.66 IC2.2 | IC2.2
N$52
  Bottom 0.61: 108.9,30.8 | K81.O1 108.9,30.8 | 108.9,30.8 110.81,32.7 118.59,32.7 121.28,30 130.49,30 131.92,30 136.05,24.77 X82.2 | X82.2
N$53
  Bottom 0.61: K82.S1 122.24,38.89 125.89,35.24 137.32,35.24 137.32,35.08 137.64,34.77 | 137.64,34.77 | 137.64,34.77 X84.1
N$54
  Bottom 0.61: D80.1 129.22,23.02 K80.16 123.98,15.24 117,15.24 LD80.K | 115.25,2.54 72.39,2.54 T80.C | 115.25,2.54 | 115.25,2.54 116.36,3.65 LD80.K | LD80.K
N$55
  Bottom 0.61: K82.O1 123.35,43.97 125.73,41.59 132.87,41.59 134.62,39.85 137.79,39.85 137.74,39.9 X84.2
N$56
  Bottom 0.61: R81.2 62.07,11.11 71.75,20.8 85.57,20.8 94.61,29.84 94.61,46.83 97.31,49.53 T81.B | T81.B
N$57
  Bottom 0.61: K82.S2 132.72,38.89 134.3,37.31 150.02,37.31 152.56,34.77 155.42,34.77 X85.1 155.42,34.92
N$58
  Bottom 0.61: K82.O2 132.56,43.97 134.14,42.39 149.86,42.39 152.4,39.85 155.42,39.85 X85.2
N$59
  Bottom 0.61: K81.16 116.52,42.86 | K81.16 114.3,41.12 104.78,41.12 101.92,43.97 T81.C | K81.16 | K81.16 | K81.16 | K81.16 D81.1 | T81.C 102.08,47.15 | T81.C | LD81.K 107.79,48.1 106.68,46.99 102.08,46.99 101.92,47.15 | 101.92,47.15 | T81.C 101.92,47.15
N$60
  Bottom 0.61: R83.1 116.05,20.64 | R83.1 | LD80.A 116.36,20.32 R83.1
N$61
  Bottom 0.406: Ü1.2 96.2,15.56 94.93,14.29 94.93,11.75 96.04,10.64 97.63,10.64 Ü1.4
  Bottom 0.61: Ü1.4 | Ü1.4
N$62
  Bottom 0.61: R80.2 60.33,4.6 61.28,3.65 65.25,3.65 66.2,4.6 T80.B
N$63
  Bottom 0.61: R82.2 69.85,32.86 75.41,38.42 81.12,38.42 96.84,54.13 T82.B
N$64
  Bottom 0.61: R4.E | Ü1.5 98.58,7.94 R4.E | 101.76,10.95 | 101.76,10.95 R4.E | R4.E 101.76,10.95 | 93.82,7.94 | 93.82,7.94 R5.2 Ü1.5 | JP2.1 92.71,6.83 93.82,7.94 | Ü1.5
N$65
  Bottom 0.61: R13.1 | R13.1 C11.2
N$66
  Bottom 0.61: Ü1.1 | Ü1.1 | R4.A | Ü1.1 99.54,18.1 R4.A | R4.A | R5.1 Ü1.1 | R5.1 | R5.1 89.38,13.81 JP2.2
N$67
  Bottom 1.016: C70.1 148.27,75.56 C73.+ 148.27,84.93 | 148.27,84.93 | IC7.IN | 148.27,84.93 IC7.IN | D71.C | D71.C 152.56,77.63 149.86,74.93 C70.1 | C70.1
N$68
  Bottom 0.61: R12.S | C11.1 86.52,75.41 R12.S
N$69
  Bottom 0.61: K82.16 129.38,56.83 D82.1 131.44,59.05 131.76,58.74 LD82.K | 129.54,56.83 K82.16 | K82.16 | K82.16 127.48,54.61 118.43,54.61 115.57,51.75 113.51,51.75 T82.C | T82.C
N$70
  Bottom 0.813: LD70.K 121.92,79.06 R70.2
N$71
  Bottom 0.61: 35.4,7.46 | 35.4,7.46 LD10.A 38.58,7.3 D10.2 | 35.4,7.46 C14.1
N$72
  Bottom 0.61: C10.1 | R10.S | R10.S C10.1
N$73
  Bottom 0.61: 21.59,83.98 21.91,83.98 24.13,86.2 24.13,90.01 22.7,91.44 22.7,93.66 23.81,94.77 25.24,94.77 C22.+ | 21.59,83.98 IC5.2 21.59,83.98 | 21.59,83.98 | 21.59,83.98 21.59,83.82
N$74
  Bottom 0.406: IC5.6 22.86,73.82 25.24,71.44 25.24,66.99 23.5,65.25 | 23.5,65.25 | 23.5,65.25 23.5,64.77 25.4,62.87 C23.-
  Bottom 0.61: IC5.6 | IC5.6
N$75
  Bottom 0.61: C63.2 111.92,61.75 110.81,60.64 109.54,60.64 R63.2
N$76
  Bottom 0.61: R61.2 91.44,67.63 97,73.18 100.97,73.18 102.08,74.3 103.66,74.3 IC6.2
N$77
  Bottom 0.813: R62.E 99.22,77.15 101.12,79.06 114.14,79.06 C62.- | C62.-
N$78
  Bottom 0.61: IC3.7 12.54,46.35 12.06,46.83 SJ30.1 10.76,46.86 10.16,47.47 10.16,49.37 R34.1 | R34.1 | R33.1 | R34.1 13.65,53.82 R33.1
N$79
  Bottom 0.61: LD11.A 34.92,56.67 D11.2 36.67,58.26 C15.1 | C15.1
N$81
  Bottom 0.61: 104.78,62.23 | C61.1 104.78,62.23 | 104.78,62.23 104.46,62.55 104.46,65.56 106.84,67.94 106.84,72.07 109.06,74.3 IC6.7
  Bottom 0.813: IC6.7
N$82
  Bottom 0.813: C62.+ 118.27,65.72 114.78,69.22 IC6.5 | C62.+ 122.4,63.34 R63.1 | C62.+ 122.4,65.88 | C62.+ | IC6.5
N$83  (via drill 1.02 pad 1.78)
  Bottom 0.61: 107.95,7.94 v110.65,7.94
N$84
  Bottom 0.61: IC1.13 22.7,17.62 28.42,11.91 P4.MP
N$85
  Bottom 0.406: IC1.11 15.72,22.7 12.54,19.53 P3.MP | P3.MP
N$86
  Bottom 0.406: IC1.5 | IC1.5
  Bottom 0.61: P2.MP 21.11,38.26 IC1.5
N$87
  Bottom 0.406: IC1.4 24.61,40.48 25.88,41.75 32.54,41.75 32.7,41.91 P1.MP
N$88
  Bottom 0.61: LD81.A 109.7,50.64 110.81,49.69 R84.1
N$89
  Bottom 0.61: R14.2 | R14.2 R15.S
N$90
  Bottom 0.61: 137.16,59.53 R85.1 LD82.A
P1
  Bottom 0: IC1.17 | IC1.17 30.64,20.16 | R80.1
  Bottom 0.406: X0.4 43.5,29.05 42.23,27.78 42.23,14.76 43.97,13.02 51.59,13.02 52.55,12.06 52.55,9.53 R80.1
  Bottom 0.61: 30.64,20.16 36.35,20.16 37.94,18.57 37.94,14.29 45.09,7.14 R80.1
P2
  Bottom 0.406: IC1.18 27.3,22.7 26.35,23.65 26.35,25.4 27.46,26.51 34.13,26.51 39.53,31.91 X0.1 | 29.21,22.7 29.21,22.86 IC1.18 | IC1.18
  Bottom 0.61: 29.21,22.7 35.4,22.7 37.15,22.7 39.85,20 39.85,15.08 43.66,11.27 50.16,11.27 R81.1
P3
  Bottom 0.406: IC1.19 | IC1.19 29.21,25.08 34.61,25.08 38.89,29.37 X0.3 | X0.3 | X0.3 41.27,29.37 42.55,30.64 52.39,30.64 54.77,33.02 R82.1
PTT-ST
  Bottom 0.61: IC1.14 21.59,15.08 26.67,10 26.67,8.89 26.83,8.73 R2.1
PTT-TX
  Bottom 0.61: X71.2 | D72.2 8.1,14.13 X71.2 | X71.2 13.49,9.37 16.35,12.22 20.16,12.22 D2.C | D2.C | D2.C 26.83,5.56 26.83,4.76 T1.C
RB
  Bottom 0.61: 35.4,17.46 | 35.4,17.46 R14.1 C14.2 | IC1.16 35.24,17.62 35.4,17.46 | C14.2
REL+
  Bottom 0.61: K80.1 D80.2 108.11,22.86 105.89,25.08 105.89,36.83 108.58,39.53 117.32,39.53 119.38,41.59 119.38,46.67 118.11,47.94 115.09,47.94 R84.2 | K81.1 108.9,43.5 D81.2 112.87,45.72 113.82,46.67 R84.2 | K80.1 | R83.2 K80.1 | R84.2 | R84.2 119.38,52.23 135.41,52.23 137.64,50.01 | 137.64,50.01 | 137.64,50.01 X84.4 | D82.2
  Bottom 0.813: K82.1 | D82.2 121.76,56.83 K82.1
  Bottom 1.016: D70.C | D70.C 155.42,74.61 148.11,67.31 | D82.2 | D82.2 125.41,62.71 136.84,62.71 143.67,55.88 D73.C | 148.11,67.31 | 148.11,67.31 C71.+ C72.1 148.27,59.37 144.15,55.24 | R85.2 | R85.2 137.48,56.52 137.48,50.01 137.64,49.85 | 144.15,55.24 | D73.C 144.15,55.24 | 137.64,49.85 143.03,55.24 D73.C | X84.4 137.64,49.85 | D73.C
RESET
  Bottom 0.61: IC3.5 16.35,41.27 17.78,42.7 17.78,46.35 19.53,48.1 | 21.59,48.1 | 21.59,48.1 IC1.1 | 19.53,48.1 21.59,48.1 | IC3.5 | R1.2 | C3.2 21.59,55.72 R1.2 | R1.2 18.57,49.05 19.53,48.1 | SJ1.1 15.21,41.31 IC3.5
RESET1  (via drill 0.61 pad 1.42)
  Top 0.406: v37.31,50.48 v37.31,25.08 | v3.49,50.48 v28.1,50.48
  Bottom 0.406: X0.5 39.05,26.83 v37.31,25.08 | v28.1,50.48 v37.31,50.48
  Bottom 0.61: IC3.2 | IC3.2 9.21,46.35 12.06,43.5 12.06,42.86 | 12.06,42.86 | 12.06,42.86 SJ1.2 | S30.4 4.01,63.7 3.97,63.66 6.67,60.96 | 6.67,60.96 6.67,51.75 5.4,50.48 v3.49,50.48 3.49,49.85 6.99,46.35 IC3.2 | R32.2 | R32.2 13.65,60.96 6.67,60.96 | 6.67,60.96
SQ-RX
  Bottom 0.61: R3.2 5.56,34.61 5.56,35.24 3.49,33.18 3.49,12.86 7.78,8.73 X71.1 8.57,8.73
SQUELCH
  Bottom 0.61: IC1.6 20.95,35.4 18.57,33.02 17.14,33.02 15.72,34.45 | 15.72,34.45 | R3.1 15.72,34.45 | R3.1 15.88,34.92 | C4.1 13.18,32.38 15.24,34.45 R3.1 | C4.1 | 15.72,34.92 15.72,34.77 C4.1 | R3.1 | D1.C 13.18,37.62 R3.1
STD
  Bottom 0.406: IC1.27 42.07,45.56 46.35,49.85 56.52,49.85 57.94,51.28 57.94,61.44 61.12,64.29 IC4.15 | IC4.15 | IC4.15
V+
  Bottom 1.016: 117.95,97.16 108.9,97.16 107.95,96.2 107.95,94.14 107.79,93.98 | 117.95,97.16 150.34,97.16 152.56,94.93 D71.A | 107.79,93.98 | X70.1 107.79,93.98 | D71.A | D70.A | D71.A D70.A | 117.95,97.16 C77.1
VOICE  (via drill 1.02 pad 1.78)
  Bottom 0.61: 107.95,15.72 | 107.95,15.72 Ü1.7 | 107.95,15.72 107.79,15.56 105.73,15.56 104.14,13.97 R4.S | R10.E 101.92,21.27 104.93,18.26 107.79,18.26 Ü1.P$6 | Ü1.P$6 | Ü1.P$6 | Ü1.7 | Ü1.7 Ü1.P$6 | Ü1.7 | Ü1.P$6 v110.65,18.1
VOICE-ST
  Bottom 0.61: JP3.3 57.47,19.84 54.45,16.83 54.45,4.29 JP4.2
VOICE-ST1
  Bottom 0.61: JP4.1 51.91,4.29 45.56,4.13 37.47,12.06 34.45,12.22 31.59,15.08 IC1.15 | IC1.15 | IC1.15

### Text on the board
Bottom: RELAIS- | STEUERUNG | V2.1.2 | OE5GHN
tNames: 1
